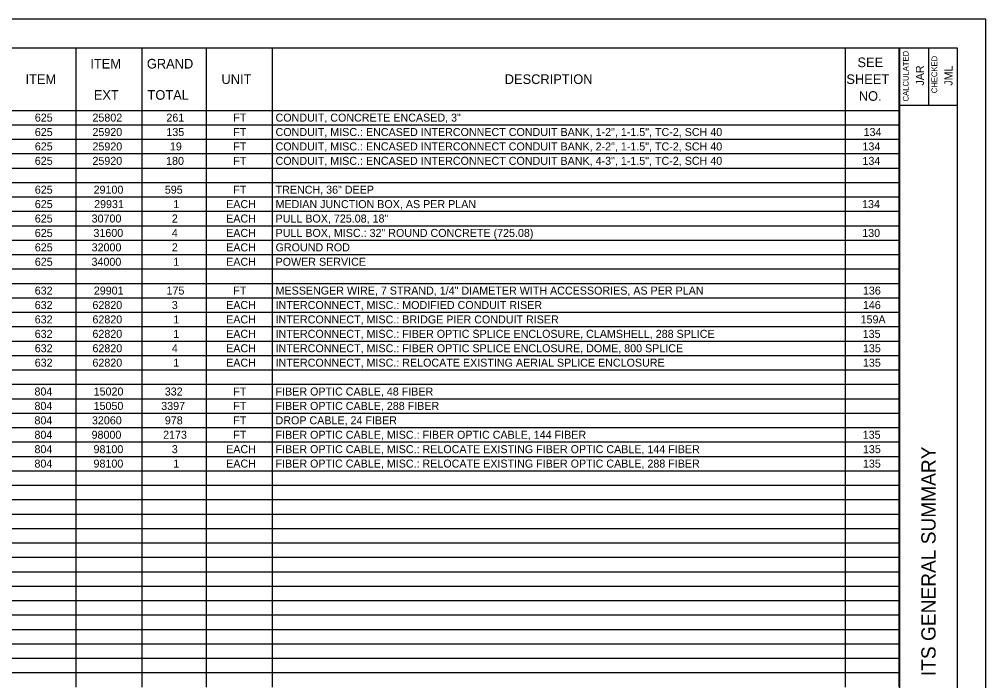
# Model space of a CAD drawing. Extents: x 1826847 to 2221677, y 500657 to 714743.
# Drawn here: x 1827702 to 1828547, y 714165 to 714743 of the extents above; entities that cross this region are included whole.
import ezdxf

# ---------------------------------------------------------------- set-up
doc = ezdxf.new("R2010")
doc.units = 0
for name, color, linetype in [('SH_Border', 7, 'Continuous'), ('SH_Cut_Line', 7, 'Continuous'), ('SH_Data', 7, 'Continuous'), ('SH_Text', 7, 'Continuous')]:
    doc.layers.add(name, color=color, linetype=linetype)

msp = doc.modelspace()

# ---------------------------------------------------------------- linework, layer by layer
at = {"layer": 'SH_Border'}
for p, q in [((1828471.62, 713668.08), (1828471.62, 714718.08)), ((1828496.62, 714718.08), (1828496.62, 714668.08)), ((1828471.62, 714668.08), (1828521.62, 714668.08))]:
    msp.add_line(p, q, dxfattribs=at)
msp.add_lwpolyline([(1826946.62, 714718.08), (1828521.62, 714718.08), (1828521.62, 713668.08), (1826946.62, 713668.08)], close=True, dxfattribs=at)
at = {"layer": 'SH_Cut_Line'}
msp.add_lwpolyline([(1826846.62, 713643.08), (1828546.62, 713643.08), (1828546.62, 714743.08), (1826846.62, 714743.08)], close=True, dxfattribs=at)
at = {"layer": 'SH_Data'}
for p, q in [((1827648.62, 714718.08), (1827808.82, 714718.08)), ((1827751.22, 714718.08), (1827751.22, 714663.48)), ((1827808.82, 714718.08), (1827865.22, 714718.08)), ((1827808.82, 714718.08), (1827808.82, 714663.48)), ((1827865.22, 714718.08), (1827922.82, 714718.08)), ((1827865.22, 714718.08), (1827865.22, 714663.48)), ((1827922.82, 714718.08), (1828470.62, 714718.08)), ((1827922.82, 714718.08), (1827922.82, 714663.48)), ((1828423.82, 714718.08), (1828423.82, 714663.48)), ((1828470.62, 714718.08), (1828470.62, 714663.48)), ((1827648.62, 714663.48), (1827808.82, 714663.48)), ((1827751.22, 714663.48), (1827751.22, 714600.48)), ((1827808.82, 714663.48), (1827865.22, 714663.48)), ((1827808.82, 714663.48), (1827808.82, 714600.48)), ((1827865.22, 714663.48), (1827922.82, 714663.48)), ((1827865.22, 714663.48), (1827865.22, 714600.48)), ((1827922.82, 714663.48), (1828470.62, 714663.48)), ((1827922.82, 714663.48), (1827922.82, 714600.48)), ((1828423.82, 714663.48), (1828423.82, 714600.48)), ((1828470.62, 714663.48), (1828470.62, 714600.48)), ((1827648.62, 714650.88), (1827808.82, 714650.88)), ((1827808.82, 714650.88), (1827865.22, 714650.88)), ((1827865.22, 714650.88), (1827922.82, 714650.88)), ((1827922.82, 714650.88), (1828470.62, 714650.88)), ((1827648.62, 714638.28), (1827808.82, 714638.28)), ((1827808.82, 714638.28), (1827865.22, 714638.28)), ((1827865.22, 714638.28), (1827922.82, 714638.28)), ((1827922.82, 714638.28), (1828470.62, 714638.28)), ((1827648.62, 714625.68), (1827808.82, 714625.68)), ((1827808.82, 714625.68), (1827865.22, 714625.68)), ((1827865.22, 714625.68), (1827922.82, 714625.68)), ((1827922.82, 714625.68), (1828470.62, 714625.68)), ((1827648.62, 714613.08), (1827808.82, 714613.08)), ((1827808.82, 714613.08), (1827865.22, 714613.08)), ((1827865.22, 714613.08), (1827922.82, 714613.08)), ((1827922.82, 714613.08), (1828470.62, 714613.08)), ((1827648.62, 714600.48), (1827808.82, 714600.48)), ((1827751.22, 714600.48), (1827751.22, 714587.88)), ((1827808.82, 714600.48), (1827865.22, 714600.48)), ((1827808.82, 714600.48), (1827808.82, 714587.88)), ((1827865.22, 714600.48), (1827922.82, 714600.48)), ((1827865.22, 714600.48), (1827865.22, 714587.88)), ((1827922.82, 714600.48), (1828470.62, 714600.48)), ((1827922.82, 714600.48), (1827922.82, 714587.88)), ((1828423.82, 714600.48), (1828423.82, 714587.88)), ((1828470.62, 714600.48), (1828470.62, 714587.88)), ((1827648.62, 714587.88), (1827808.82, 714587.88)), ((1827751.22, 714587.88), (1827751.22, 714575.28)), ((1827808.82, 714587.88), (1827865.22, 714587.88)), ((1827808.82, 714587.88), (1827808.82, 714575.28)), ((1827865.22, 714587.88), (1827922.82, 714587.88)), ((1827865.22, 714587.88), (1827865.22, 714575.28)), ((1827922.82, 714587.88), (1828470.62, 714587.88)), ((1827922.82, 714587.88), (1827922.82, 714575.28)), ((1828423.82, 714587.88), (1828423.82, 714575.28)), ((1828470.62, 714587.88), (1828470.62, 714575.28)), ((1827648.62, 714575.28), (1827808.82, 714575.28)), ((1827751.22, 714575.28), (1827751.22, 714562.68)), ((1827808.82, 714575.28), (1827865.22, 714575.28)), ((1827808.82, 714575.28), (1827808.82, 714562.68)), ((1827865.22, 714575.28), (1827922.82, 714575.28)), ((1827865.22, 714575.28), (1827865.22, 714562.68)), ((1827922.82, 714575.28), (1828470.62, 714575.28)), ((1827922.82, 714575.28), (1827922.82, 714562.68)), ((1828423.82, 714575.28), (1828423.82, 714562.68)), ((1828470.62, 714575.28), (1828470.62, 714562.68)), ((1827648.62, 714562.68), (1827808.82, 714562.68)), ((1827751.22, 714562.68), (1827751.22, 714550.08)), ((1827808.82, 714562.68), (1827865.22, 714562.68)), ((1827808.82, 714562.68), (1827808.82, 714550.08)), ((1827865.22, 714562.68), (1827922.82, 714562.68)), ((1827865.22, 714562.68), (1827865.22, 714550.08)), ((1827922.82, 714562.68), (1828470.62, 714562.68)), ((1827922.82, 714562.68), (1827922.82, 714550.08)), ((1828423.82, 714562.68), (1828423.82, 714550.08)), ((1828470.62, 714562.68), (1828470.62, 714550.08)), ((1827648.62, 714550.08), (1827808.82, 714550.08)), ((1827751.22, 714550.08), (1827751.22, 714537.48)), ((1827808.82, 714550.08), (1827865.22, 714550.08)), ((1827808.82, 714550.08), (1827808.82, 714537.48)), ((1827865.22, 714550.08), (1827922.82, 714550.08)), ((1827865.22, 714550.08), (1827865.22, 714537.48)), ((1827922.82, 714550.08), (1828470.62, 714550.08)), ((1827922.82, 714550.08), (1827922.82, 714537.48)), ((1828423.82, 714550.08), (1828423.82, 714537.48)), ((1828470.62, 714550.08), (1828470.62, 714537.48)), ((1827648.62, 714537.48), (1827808.82, 714537.48)), ((1827751.22, 714537.48), (1827751.22, 714524.88)), ((1827808.82, 714537.48), (1827865.22, 714537.48)), ((1827808.82, 714537.48), (1827808.82, 714524.88)), ((1827865.22, 714537.48), (1827922.82, 714537.48)), ((1827865.22, 714537.48), (1827865.22, 714524.88)), ((1827922.82, 714537.48), (1828470.62, 714537.48)), ((1827922.82, 714537.48), (1827922.82, 714524.88)), ((1828423.82, 714537.48), (1828423.82, 714524.88)), ((1828470.62, 714537.48), (1828470.62, 714524.88)), ((1827648.62, 714524.88), (1827808.82, 714524.88)), ((1827751.22, 714524.88), (1827751.22, 714512.28)), ((1827808.82, 714524.88), (1827865.22, 714524.88)), ((1827808.82, 714524.88), (1827808.82, 714512.28)), ((1827865.22, 714524.88), (1827922.82, 714524.88)), ((1827865.22, 714524.88), (1827865.22, 714512.28)), ((1827922.82, 714524.88), (1828470.62, 714524.88)), ((1827922.82, 714524.88), (1827922.82, 714512.28)), ((1828423.82, 714524.88), (1828423.82, 714512.28)), ((1828470.62, 714524.88), (1828470.62, 714512.28)), ((1827648.62, 714512.28), (1827808.82, 714512.28)), ((1827751.22, 714512.28), (1827751.22, 714499.68)), ((1827808.82, 714512.28), (1827865.22, 714512.28)), ((1827808.82, 714512.28), (1827808.82, 714499.68)), ((1827865.22, 714512.28), (1827922.82, 714512.28)), ((1827865.22, 714512.28), (1827865.22, 714499.68)), ((1827922.82, 714512.28), (1828470.62, 714512.28)), ((1827922.82, 714512.28), (1827922.82, 714499.68)), ((1828423.82, 714512.28), (1828423.82, 714499.68)), ((1828470.62, 714512.28), (1828470.62, 714499.68)), ((1827648.62, 714499.68), (1827808.82, 714499.68)), ((1827751.22, 714499.68), (1827751.22, 714487.08)), ((1827808.82, 714499.68), (1827865.22, 714499.68)), ((1827808.82, 714499.68), (1827808.82, 714487.08)), ((1827865.22, 714499.68), (1827922.82, 714499.68)), ((1827865.22, 714499.68), (1827865.22, 714487.08)), ((1827922.82, 714499.68), (1828470.62, 714499.68)), ((1827922.82, 714499.68), (1827922.82, 714487.08)), ((1828423.82, 714499.68), (1828423.82, 714487.08)), ((1828470.62, 714499.68), (1828470.62, 714487.08)), ((1827648.62, 714487.08), (1827808.82, 714487.08)), ((1827751.22, 714487.08), (1827751.22, 714474.48)), ((1827808.82, 714487.08), (1827865.22, 714487.08)), ((1827808.82, 714487.08), (1827808.82, 714474.48)), ((1827865.22, 714487.08), (1827922.82, 714487.08)), ((1827865.22, 714487.08), (1827865.22, 714474.48)), ((1827922.82, 714487.08), (1828470.62, 714487.08)), ((1827922.82, 714487.08), (1827922.82, 714474.48)), ((1828423.82, 714487.08), (1828423.82, 714474.48)), ((1828470.62, 714487.08), (1828470.62, 714474.48)), ((1827648.62, 714474.48), (1827808.82, 714474.48)), ((1827751.22, 714474.48), (1827751.22, 714461.88)), ((1827808.82, 714474.48), (1827865.22, 714474.48)), ((1827808.82, 714474.48), (1827808.82, 714461.88)), ((1827865.22, 714474.48), (1827922.82, 714474.48)), ((1827865.22, 714474.48), (1827865.22, 714461.88)), ((1827922.82, 714474.48), (1828470.62, 714474.48)), ((1827922.82, 714474.48), (1827922.82, 714461.88)), ((1828423.82, 714474.48), (1828423.82, 714461.88)), ((1828470.62, 714474.48), (1828470.62, 714461.88)), ((1827648.62, 714461.88), (1827808.82, 714461.88)), ((1827751.22, 714461.88), (1827751.22, 714424.08)), ((1827808.82, 714461.88), (1827865.22, 714461.88)), ((1827808.82, 714461.88), (1827808.82, 714424.08)), ((1827865.22, 714461.88), (1827922.82, 714461.88)), ((1827865.22, 714461.88), (1827865.22, 714424.08)), ((1827922.82, 714461.88), (1828470.62, 714461.88)), ((1827922.82, 714461.88), (1827922.82, 714424.08)), ((1828423.82, 714461.88), (1828423.82, 714424.08)), ((1828470.62, 714461.88), (1828470.62, 714424.08)), ((1827648.62, 714449.28), (1827808.82, 714449.28)), ((1827808.82, 714449.28), (1827865.22, 714449.28)), ((1827865.22, 714449.28), (1827922.82, 714449.28)), ((1827922.82, 714449.28), (1828470.62, 714449.28)), ((1827648.62, 714436.68), (1827808.82, 714436.68)), ((1827808.82, 714436.68), (1827865.22, 714436.68)), ((1827865.22, 714436.68), (1827922.82, 714436.68)), ((1827922.82, 714436.68), (1828470.62, 714436.68)), ((1827648.62, 714424.08), (1827808.82, 714424.08)), ((1827751.22, 714424.08), (1827751.22, 714398.88)), ((1827808.82, 714424.08), (1827865.22, 714424.08)), ((1827808.82, 714424.08), (1827808.82, 714398.88)), ((1827865.22, 714424.08), (1827922.82, 714424.08)), ((1827865.22, 714424.08), (1827865.22, 714398.88)), ((1827922.82, 714424.08), (1828470.62, 714424.08)), ((1827922.82, 714424.08), (1827922.82, 714398.88)), ((1828423.82, 714424.08), (1828423.82, 714398.88)), ((1828470.62, 714424.08), (1828470.62, 714398.88)), ((1827648.62, 714411.48), (1827808.82, 714411.48)), ((1827808.82, 714411.48), (1827865.22, 714411.48)), ((1827865.22, 714411.48), (1827922.82, 714411.48)), ((1827922.82, 714411.48), (1828470.62, 714411.48)), ((1827648.62, 714398.88), (1827808.82, 714398.88)), ((1827751.22, 714398.88), (1827751.22, 714361.08)), ((1827808.82, 714398.88), (1827865.22, 714398.88)), ((1827808.82, 714398.88), (1827808.82, 714361.08)), ((1827865.22, 714398.88), (1827922.82, 714398.88)), ((1827865.22, 714398.88), (1827865.22, 714361.08)), ((1827922.82, 714398.88), (1828470.62, 714398.88)), ((1827922.82, 714398.88), (1827922.82, 714361.08)), ((1828423.82, 714398.88), (1828423.82, 714361.08)), ((1828470.62, 714398.88), (1828470.62, 714361.08)), ((1827648.62, 714386.28), (1827808.82, 714386.28)), ((1827808.82, 714386.28), (1827865.22, 714386.28)), ((1827865.22, 714386.28), (1827922.82, 714386.28)), ((1827922.82, 714386.28), (1828470.62, 714386.28)), ((1827648.62, 714373.68), (1827808.82, 714373.68)), ((1827808.82, 714373.68), (1827865.22, 714373.68)), ((1827865.22, 714373.68), (1827922.82, 714373.68)), ((1827922.82, 714373.68), (1828470.62, 714373.68)), ((1827648.62, 714361.08), (1827808.82, 714361.08)), ((1827751.22, 714361.08), (1827751.22, 714335.88)), ((1827808.82, 714361.08), (1827865.22, 714361.08)), ((1827808.82, 714361.08), (1827808.82, 714335.88)), ((1827865.22, 714361.08), (1827922.82, 714361.08)), ((1827865.22, 714361.08), (1827865.22, 714335.88)), ((1827922.82, 714361.08), (1828470.62, 714361.08)), ((1827922.82, 714361.08), (1827922.82, 714335.88)), ((1828423.82, 714361.08), (1828423.82, 714335.88)), ((1828470.62, 714361.08), (1828470.62, 714335.88)), ((1827648.62, 714348.48), (1827808.82, 714348.48)), ((1827808.82, 714348.48), (1827865.22, 714348.48)), ((1827865.22, 714348.48), (1827922.82, 714348.48)), ((1827922.82, 714348.48), (1828470.62, 714348.48)), ((1827648.62, 714335.88), (1827808.82, 714335.88)), ((1827751.22, 714335.88), (1827751.22, 714298.08)), ((1827808.82, 714335.88), (1827865.22, 714335.88)), ((1827808.82, 714335.88), (1827808.82, 714298.08)), ((1827865.22, 714335.88), (1827922.82, 714335.88)), ((1827865.22, 714335.88), (1827865.22, 714298.08)), ((1827922.82, 714335.88), (1828470.62, 714335.88)), ((1827922.82, 714335.88), (1827922.82, 714298.08)), ((1828423.82, 714335.88), (1828423.82, 714298.08)), ((1828470.62, 714335.88), (1828470.62, 714298.08)), ((1827648.62, 714323.28), (1827808.82, 714323.28)), ((1827808.82, 714323.28), (1827865.22, 714323.28)), ((1827865.22, 714323.28), (1827922.82, 714323.28)), ((1827922.82, 714323.28), (1828470.62, 714323.28)), ((1827648.62, 714310.68), (1827808.82, 714310.68)), ((1827808.82, 714310.68), (1827865.22, 714310.68)), ((1827865.22, 714310.68), (1827922.82, 714310.68)), ((1827922.82, 714310.68), (1828470.62, 714310.68)), ((1827648.62, 714298.08), (1827808.82, 714298.08)), ((1827751.22, 714298.08), (1827751.22, 714285.48)), ((1827808.82, 714298.08), (1827865.22, 714298.08)), ((1827808.82, 714298.08), (1827808.82, 714285.48)), ((1827865.22, 714298.08), (1827922.82, 714298.08)), ((1827865.22, 714298.08), (1827865.22, 714285.48)), ((1827922.82, 714298.08), (1828470.62, 714298.08)), ((1827922.82, 714298.08), (1827922.82, 714285.48)), ((1828423.82, 714298.08), (1828423.82, 714285.48)), ((1828470.62, 714298.08), (1828470.62, 714285.48)), ((1827648.62, 714285.48), (1827808.82, 714285.48)), ((1827751.22, 714285.48), (1827751.22, 714222.48)), ((1827808.82, 714285.48), (1827865.22, 714285.48)), ((1827808.82, 714285.48), (1827808.82, 714222.48)), ((1827865.22, 714285.48), (1827922.82, 714285.48)), ((1827865.22, 714285.48), (1827865.22, 714222.48)), ((1827922.82, 714285.48), (1828470.62, 714285.48)), ((1827922.82, 714285.48), (1827922.82, 714222.48)), ((1828423.82, 714285.48), (1828423.82, 714222.48)), ((1828470.62, 714285.48), (1828470.62, 714222.48)), ((1827648.62, 714272.88), (1827808.82, 714272.88)), ((1827808.82, 714272.88), (1827865.22, 714272.88)), ((1827865.22, 714272.88), (1827922.82, 714272.88)), ((1827922.82, 714272.88), (1828470.62, 714272.88)), ((1827648.62, 714260.28), (1827808.82, 714260.28)), ((1827808.82, 714260.28), (1827865.22, 714260.28)), ((1827865.22, 714260.28), (1827922.82, 714260.28)), ((1827922.82, 714260.28), (1828470.62, 714260.28)), ((1827648.62, 714247.68), (1827808.82, 714247.68)), ((1827808.82, 714247.68), (1827865.22, 714247.68)), ((1827865.22, 714247.68), (1827922.82, 714247.68)), ((1827922.82, 714247.68), (1828470.62, 714247.68)), ((1827648.62, 714235.08), (1827808.82, 714235.08)), ((1827808.82, 714235.08), (1827865.22, 714235.08)), ((1827865.22, 714235.08), (1827922.82, 714235.08)), ((1827922.82, 714235.08), (1828470.62, 714235.08)), ((1827648.62, 714222.48), (1827808.82, 714222.48)), ((1827751.22, 714222.48), (1827751.22, 714159.48)), ((1827808.82, 714222.48), (1827865.22, 714222.48)), ((1827808.82, 714222.48), (1827808.82, 714159.48)), ((1827865.22, 714222.48), (1827922.82, 714222.48)), ((1827865.22, 714222.48), (1827865.22, 714159.48)), ((1827922.82, 714222.48), (1828470.62, 714222.48)), ((1827922.82, 714222.48), (1827922.82, 714159.48)), ((1828423.82, 714222.48), (1828423.82, 714159.48)), ((1828470.62, 714222.48), (1828470.62, 714159.48)), ((1827648.62, 714209.88), (1827808.82, 714209.88)), ((1827808.82, 714209.88), (1827865.22, 714209.88)), ((1827865.22, 714209.88), (1827922.82, 714209.88)), ((1827922.82, 714209.88), (1828470.62, 714209.88)), ((1827648.62, 714197.28), (1827808.82, 714197.28)), ((1827808.82, 714197.28), (1827865.22, 714197.28)), ((1827865.22, 714197.28), (1827922.82, 714197.28)), ((1827922.82, 714197.28), (1828470.62, 714197.28)), ((1827648.62, 714184.68), (1827808.82, 714184.68)), ((1827808.82, 714184.68), (1827865.22, 714184.68)), ((1827865.22, 714184.68), (1827922.82, 714184.68)), ((1827922.82, 714184.68), (1828470.62, 714184.68)), ((1827648.62, 714172.08), (1827808.82, 714172.08)), ((1827808.82, 714172.08), (1827865.22, 714172.08)), ((1827865.22, 714172.08), (1827922.82, 714172.08)), ((1827922.82, 714172.08), (1828470.62, 714172.08))]:
    msp.add_line(p, q, dxfattribs=at)

# ---------------------------------------------------------------- texts
for s, height, p in [('CALCULATED', 5, (1828479.24, 714671.31)), ('CHECKED', 5, (1828504.24, 714678.47)), ('JAR', 7, (1828492.62, 714685.16)), ('JML', 7, (1828517.62, 714685.04)), ('ITS GENERAL SUMMARY', 12.5, (1828502.87, 714169.07))]:
    msp.add_text(s, height=height, rotation=90, dxfattribs=at).set_placement(p)
for s, p in [('134', (1828439.89, 714641.08)), ('134', (1828438.89, 714628.48)), ('134', (1828438.89, 714615.88)), ('134', (1828438.56, 714578.08)), ('130', (1828438.69, 714552.88)), ('136', (1828439.28, 714502.48)), ('146', (1828439.3, 714489.88)), ('159A', (1828437.27, 714477.28)), ('135', (1828439.11, 714464.68)), ('135', (1828439.3, 714452.08)), ('135', (1828439.3, 714439.48)), ('135', (1828439.11, 714376.48)), ('135', (1828439.3, 714363.88)), ('135', (1828439.3, 714351.28))]:
    msp.add_text(s, height=7, dxfattribs=at).set_placement(p)
at = {"layer": 'SH_Text'}
for s, height, p in [('ITEM', 8.4, (1827763.88, 714700.08)), ('GRAND', 8.4, (1827813.3, 714700.08)), ('SEE', 8.4, (1828434.55, 714701.28)), ('ITEM', 8.4, (1827707.18, 714686.58)), ('UNIT', 8.4, (1827878.51, 714686.58)), ('DESCRIPTION', 8.4, (1828126.16, 714686.58)), ('SHEET', 8.4, (1828424.83, 714686.58)), ('EXT', 8.4, (1827766.92, 714672.78)), ('TOTAL', 8.4, (1827813.87, 714672.78)), ('NO.', 8.4, (1828435.71, 714671.88)), ('625', 7, (1827715.35, 714653.68)), ('25802', 7, (1827765.74, 714653.68)), ('261', 7, (1827830.37, 714653.68)), ('FT', 7, (1827888.84, 714653.68)), ('CONDUIT, CONCRETE ENCASED, 3"', 7, (1827925.82, 714653.68)), ('625', 7, (1827715.35, 714641.08)), ('25920', 7, (1827765.74, 714641.08)), ('135', 7, (1827830.38, 714641.08)), ('FT', 7, (1827888.84, 714641.08)), ('CONDUIT, MISC.: ENCASED INTERCONNECT CONDUIT BANK, 1-2", 1-1.5", TC-2, SCH 40', 7, (1827925.82, 714641.08)), ('625', 7, (1827715.35, 714628.48)), ('25920', 7, (1827765.74, 714628.48)), ('19', 7, (1827833.44, 714628.48)), ('FT', 7, (1827888.84, 714628.48)), ('CONDUIT, MISC.: ENCASED INTERCONNECT CONDUIT BANK, 2-2", 1-1.5", TC-2, SCH 40', 7, (1827925.82, 714628.48)), ('625', 7, (1827715.35, 714615.88)), ('25920', 7, (1827765.74, 714615.88)), ('180', 7, (1827830.13, 714615.88)), ('FT', 7, (1827888.84, 714615.88)), ('CONDUIT, MISC.: ENCASED INTERCONNECT CONDUIT BANK, 4-3", 1-1.5", TC-2, SCH 40', 7, (1827925.82, 714615.88)), ('625', 7, (1827715.35, 714590.68)), ('29100', 7, (1827766.74, 714590.68)), ('595', 7, (1827829, 714590.68)), ('FT', 7, (1827888.84, 714590.68)), ('TRENCH, 36" DEEP', 7, (1827925.82, 714590.68)), ('625', 7, (1827715.35, 714578.08)), ('29931', 7, (1827767.2, 714578.08)), ('1', 7, (1827836.43, 714578.08)), ('EACH', 7, (1827882.64, 714578.08)), ('MEDIAN JUNCTION BOX, AS PER PLAN', 7, (1827925.82, 714578.08)), ('625', 7, (1827715.35, 714565.48)), ('30700', 7, (1827765.02, 714565.48)), ('2', 7, (1827835.14, 714565.48)), ('EACH', 7, (1827882.64, 714565.48)), ('PULL BOX, 725.08, 18"', 7, (1827925.82, 714565.48)), ('625', 7, (1827715.35, 714552.88)), ('31600', 7, (1827766.62, 714552.88)), ('4', 7, (1827835.14, 714552.88)), ('EACH', 7, (1827882.64, 714552.88)), ('PULL BOX, MISC.: 32" ROUND CONCRETE (725.08)', 7, (1827925.82, 714552.88)), ('625', 7, (1827715.35, 714540.28)), ('32000', 7, (1827765.02, 714540.28)), ('2', 7, (1827835.14, 714540.28)), ('EACH', 7, (1827882.64, 714540.28)), ('GROUND ROD', 7, (1827925.82, 714540.28)), ('625', 7, (1827715.35, 714527.68)), ('34000', 7, (1827764.94, 714527.68)), ('1', 7, (1827836.43, 714527.68)), ('EACH', 7, (1827882.64, 714527.68)), ('POWER SERVICE', 7, (1827925.82, 714527.68)), ('632', 7, (1827715.27, 714502.48)), ('29901', 7, (1827766.92, 714502.48)), ('175', 7, (1827830.49, 714502.48)), ('FT', 7, (1827888.84, 714502.48)), ('MESSENGER WIRE, 7 STRAND, 1/4" DIAMETER WITH ACCESSORIES, AS PER PLAN', 7, (1827925.82, 714502.48)), ('632', 7, (1827715.27, 714489.88)), ('62820', 7, (1827765.74, 714489.88)), ('3', 7, (1827835.11, 714489.88)), ('EACH', 7, (1827882.64, 714489.88)), ('INTERCONNECT, MISC.: MODIFIED CONDUIT RISER', 7, (1827925.82, 714489.88)), ('632', 7, (1827715.27, 714477.28)), ('62820', 7, (1827765.74, 714477.28)), ('1', 7, (1827836.43, 714477.28)), ('EACH', 7, (1827882.64, 714477.28)), ('INTERCONNECT, MISC.: BRIDGE PIER CONDUIT RISER', 7, (1827925.82, 714477.28)), ('632', 7, (1827715.27, 714464.68)), ('62820', 7, (1827765.74, 714464.68)), ('1', 7, (1827836.43, 714464.68)), ('EACH', 7, (1827882.64, 714464.68)), ('INTERCONNECT, MISC.: FIBER OPTIC SPLICE ENCLOSURE, CLAMSHELL, 288 SPLICE', 7, (1827925.82, 714464.68)), ('632', 7, (1827715.27, 714452.08)), ('62820', 7, (1827765.74, 714452.08)), ('4', 7, (1827835.14, 714452.08)), ('EACH', 7, (1827882.64, 714452.08)), ('INTERCONNECT, MISC.: FIBER OPTIC SPLICE ENCLOSURE, DOME, 800 SPLICE', 7, (1827925.82, 714452.08)), ('632', 7, (1827715.27, 714439.48)), ('62820', 7, (1827765.74, 714439.48)), ('1', 7, (1827836.43, 714439.48)), ('EACH', 7, (1827882.64, 714439.48)), ('INTERCONNECT, MISC.: RELOCATE EXISTING AERIAL SPLICE ENCLOSURE', 7, (1827925.82, 714439.48)), ('804', 7, (1827715.05, 714414.28)), ('15020', 7, (1827766.79, 714414.28)), ('332', 7, (1827828.97, 714414.28)), ('FT', 7, (1827888.84, 714414.28)), ('FIBER OPTIC CABLE, 48 FIBER', 7, (1827925.82, 714414.28)), ('804', 7, (1827715.05, 714401.68)), ('15050', 7, (1827766.74, 714401.68)), ('3397', 7, (1827825.86, 714401.68)), ('FT', 7, (1827888.84, 714401.68)), ('FIBER OPTIC CABLE, 288 FIBER', 7, (1827925.82, 714401.68)), ('804', 7, (1827715.05, 714389.08)), ('32060', 7, (1827765.3, 714389.08)), ('978', 7, (1827829.02, 714389.08)), ('FT', 7, (1827888.84, 714389.08)), ('DROP CABLE, 24 FIBER', 7, (1827925.82, 714389.08)), ('804', 7, (1827715.05, 714376.48)), ('98000', 7, (1827764.97, 714376.48)), ('2173', 7, (1827827.51, 714376.48)), ('FT', 7, (1827888.84, 714376.48)), ('FIBER OPTIC CABLE, MISC.: FIBER OPTIC CABLE, 144 FIBER', 7, (1827925.82, 714376.48)), ('804', 7, (1827715.05, 714363.88)), ('98100', 7, (1827766.68, 714363.88)), ('3', 7, (1827835.11, 714363.88)), ('EACH', 7, (1827882.64, 714363.88)), ('FIBER OPTIC CABLE, MISC.: RELOCATE EXISTING FIBER OPTIC CABLE, 144 FIBER', 7, (1827925.82, 714363.88)), ('804', 7, (1827715.05, 714351.28)), ('98100', 7, (1827766.68, 714351.28)), ('1', 7, (1827836.43, 714351.28)), ('EACH', 7, (1827882.64, 714351.28)), ('FIBER OPTIC CABLE, MISC.: RELOCATE EXISTING FIBER OPTIC CABLE, 288 FIBER', 7, (1827925.82, 714351.28))]:
    msp.add_text(s, height=height, dxfattribs=at).set_placement(p)

doc.saveas('drawing.dxf')
